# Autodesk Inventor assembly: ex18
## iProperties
Shininess: 64.0
Length Units: 11272
Angle Units: 11279
Time Units: 11290
Mass Units: 11286
Length Display Precision: 3
Angle Display Precision: 2
Compacted: True
Part Number: ex18
Document SubType Name: Assembly
Created: 2002-11
Designer: E. MOSS
Density: 0.0
Volumn: 0.0
Area: 0.0
PropertySet Name: Model Information
Control State: 0
Master: False
Checked Out: False
Author: E. MOSS
